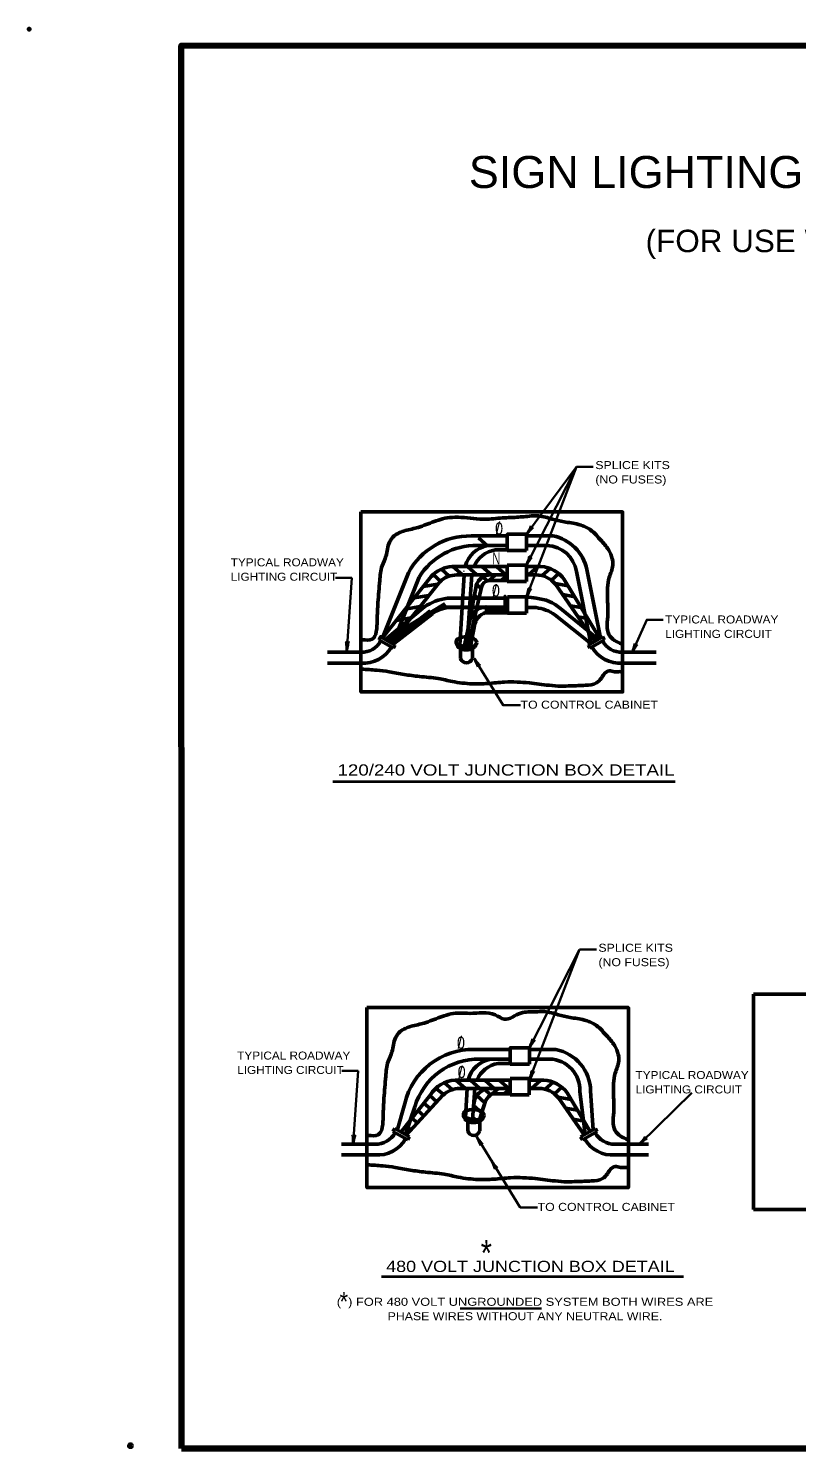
# Model space of a CAD drawing. Extents: x -38 to 818, y -13 to 531.
# Drawn here: x -38 to 250, y -2 to 531 of the extents above; entities that cross this region are included whole.
import ezdxf
from ezdxf.enums import TextEntityAlignment as Align

# ---------------------------------------------------------------- set-up
doc = ezdxf.new("R2010")
doc.units = 0
doc.header["$LTSCALE"] = 1.2
doc.header["$PDMODE"] = 32
doc.header["$PDSIZE"] = 0.6
doc.layers.add('1', color=7, linetype='Continuous', lineweight=53)

msp = doc.modelspace()

# ---------------------------------------------------------------- hatches: boundary and pattern name
at = {"layer": '1'}
for points in [[(0.944, -0.654, 1), (-0.256, -0.654, 1)], [(0.944, -0.654, 1), (-0.256, -0.654, 1)], [(1.089, -0.622, 1), (-0.111, -0.622, 1)], [(1.091, -0.622, 1), (-0.109, -0.622, 1)], [(1.121, -0.654, 1), (-0.079, -0.654, 1)], [(1.121, -0.654, 1), (-0.079, -0.654, 1)]]:
    msp.add_hatch(color=256, dxfattribs=at).paths.add_polyline_path(points)

# ---------------------------------------------------------------- linework, layer by layer
at = {"layer": '1', "lineweight": 35}
for p, q in [((167.736, 366.372), (148.989, 317.6)), ((167.736, 366.372), (174.011, 366.372)), ((83.465, 324.81), (77.293, 324.815)), ((81.538, 297.43), (83.465, 324.81)), ((168.893, 185.393), (150.071, 148.577)), ((168.893, 185.393), (150.146, 136.62)), ((168.893, 185.393), (175.168, 185.393)), ((85.898, 139.872), (79.726, 139.877)), ((83.97, 112.491), (85.898, 139.872)), ((191.422, 112.496), (210.938, 131.679)), ((124.08, 50.826), (154.633, 50.826))]:
    msp.add_line(p, q, dxfattribs=at)
at = {"layer": '1'}
for p, q in [((141.782, 341.134), (148.982, 341.134)), ((141.782, 341.134), (141.782, 335.015)), ((141.782, 341.134), (141.782, 335.015)), ((141.782, 341.134), (141.782, 335.015)), ((148.982, 341.134), (148.982, 335.015)), ((128.282, 340.491), (141.782, 340.491)), ((141.782, 336.891), (130.532, 336.891)), ((130.532, 336.891), (141.782, 336.891)), ((130.532, 336.891), (141.782, 336.891)), ((134.496, 336.652), (130.937, 339.805)), ((148.982, 340.491), (158.882, 340.491)), ((142.032, 335.247), (137.221, 335.247)), ((141.782, 335.015), (148.982, 335.015)), ((113.219, 325.292), (94.947, 302.337)), ((94.988, 302.314), (104.671, 326.655)), ((108.703, 325.05), (98.793, 300.139)), ((116.709, 323.553), (114.043, 325.915)), ((120.021, 325.428), (117.072, 328.041)), ((141.782, 329.013), (121.082, 329.013)), ((124.947, 325.873), (121.388, 329.027)), ((122.882, 325.873), (141.714, 325.873)), ((122.882, 325.873), (141.714, 325.873)), ((123.989, 299.51), (125.647, 325.873)), ((130.376, 325.873), (126.833, 329.013)), ((135.805, 325.873), (132.261, 329.013)), ((134.211, 323.646), (132.58, 325.091)), ((137.338, 325.873), (135.001, 323.803)), ((141.234, 325.873), (137.69, 329.013)), ((141.8, 325.873), (139.463, 323.803)), ((141.714, 329.556), (148.914, 329.556)), ((141.714, 329.556), (141.714, 323.437)), ((148.914, 329.556), (148.914, 323.437)), ((154.382, 329.013), (148.914, 329.013)), ((152.582, 325.873), (148.914, 325.873)), ((149.734, 325.873), (153.278, 329.013)), ((154.851, 325.597), (157.858, 328.261)), ((158.341, 323.88), (161.129, 326.349)), ((173.097, 300.165), (167.719, 327.102)), ((171.589, 327.875), (176.71, 302.229)), ((116.474, 323.315), (98.265, 300.441)), ((110.178, 321.471), (115.763, 322.422)), ((132.128, 321.254), (126.979, 298.623)), ((129.918, 320.961), (127.136, 305.98)), ((132.02, 320.778), (130.263, 322.334)), ((135.059, 323.803), (141.714, 323.803)), ((141.714, 323.437), (148.914, 323.437)), ((164.601, 321.77), (159.688, 322.606)), ((159.85, 322.372), (174.594, 301.02)), ((163.154, 324.179), (176.434, 302.071)), ((97.045, 302.095), (118.392, 315.057)), ((97.094, 302.015), (118.44, 314.978)), ((97.137, 301.943), (118.484, 314.905)), ((97.383, 301.538), (118.73, 314.501)), ((106.815, 317.247), (112.4, 318.198)), ((119.282, 317.091), (141.789, 317.091)), ((131.109, 316.775), (129.419, 318.273)), ((140.947, 314.153), (140.947, 314.375)), ((141.789, 317.6), (148.989, 317.6)), ((141.789, 317.6), (141.789, 311.48)), ((141.789, 317.6), (141.789, 311.48)), ((148.989, 317.6), (148.989, 311.48)), ((167.045, 317.702), (162.546, 318.468)), ((169.488, 313.634), (165.403, 314.329)), ((96.065, 301.698), (110.662, 313.885)), ((97.935, 300.629), (112.393, 310.537)), ((98.47, 301.209), (112.868, 312.357)), ((98.552, 301.102), (112.95, 312.25)), ((98.671, 300.949), (113.069, 312.097)), ((98.712, 300.896), (113.11, 312.044)), ((98.723, 300.882), (113.121, 312.03)), ((98.723, 300.882), (113.121, 312.03)), ((98.865, 300.699), (113.262, 311.847)), ((98.876, 300.685), (113.273, 311.833)), ((98.898, 300.656), (113.296, 311.804)), ((98.965, 300.569), (113.363, 311.717)), ((98.965, 300.569), (113.363, 311.717)), ((99.062, 300.445), (113.459, 311.593)), ((99.095, 300.401), (113.493, 311.55)), ((99.162, 300.315), (113.56, 311.463)), ((99.185, 300.286), (113.582, 311.434)), ((99.203, 300.262), (113.601, 311.41)), ((99.304, 300.132), (113.702, 311.28)), ((100.09, 308.798), (105.675, 309.749)), ((103.452, 313.022), (109.038, 313.973)), ((141.789, 313.592), (119.282, 313.592)), ((141.789, 313.592), (119.282, 313.592)), ((141.789, 313.592), (119.282, 313.592)), ((141.789, 313.592), (119.282, 313.592)), ((125.613, 298.909), (127.809, 309.303)), ((129.216, 311.767), (128.353, 312.532)), ((133.388, 313.483), (141.783, 313.519)), ((133.388, 313.483), (141.783, 313.519)), ((133.388, 313.414), (141.783, 313.451)), ((133.388, 313.346), (141.783, 313.383)), ((133.388, 313.346), (141.783, 313.382)), ((133.388, 313.329), (141.783, 313.365)), ((133.388, 313.329), (141.783, 313.365)), ((133.389, 313.295), (141.783, 313.331)), ((133.389, 313.278), (141.784, 313.314)), ((133.389, 313.243), (141.784, 313.28)), ((133.389, 313.175), (141.784, 313.211)), ((133.389, 313.141), (141.784, 313.177)), ((133.389, 313.141), (141.784, 313.177)), ((133.39, 313.056), (141.785, 313.092)), ((133.39, 312.987), (141.785, 313.024)), ((133.39, 312.935), (141.785, 312.972)), ((133.39, 312.936), (141.785, 312.972)), ((133.39, 312.919), (141.785, 312.955)), ((133.39, 312.902), (141.785, 312.938)), ((133.391, 312.85), (141.785, 312.887)), ((133.391, 312.782), (141.786, 312.819)), ((133.391, 312.765), (141.786, 312.801)), ((133.391, 312.748), (141.786, 312.784)), ((133.391, 312.748), (141.786, 312.784)), ((133.391, 312.748), (141.786, 312.784)), ((133.391, 312.696), (141.786, 312.733)), ((133.392, 312.645), (141.786, 312.682)), ((133.392, 312.628), (141.786, 312.665)), ((133.392, 312.577), (141.787, 312.614)), ((133.392, 312.577), (141.787, 312.614)), ((133.392, 312.543), (141.787, 312.579)), ((133.392, 312.475), (141.787, 312.511)), ((133.392, 312.475), (141.787, 312.511)), ((133.392, 312.458), (141.787, 312.494)), ((133.393, 312.389), (141.787, 312.426)), ((133.393, 312.338), (141.788, 312.374)), ((133.393, 312.321), (141.788, 312.357)), ((133.393, 312.287), (141.788, 312.324)), ((133.394, 312.202), (141.788, 312.238)), ((133.394, 312.201), (141.788, 312.238)), ((133.394, 312.168), (141.788, 312.204)), ((133.394, 312.167), (141.788, 312.203)), ((133.394, 312.133), (141.788, 312.169)), ((133.394, 312.081), (141.789, 312.118)), ((133.394, 312.03), (141.789, 312.067)), ((133.394, 312.013), (141.789, 312.05)), ((133.394, 311.997), (141.789, 312.033)), ((133.394, 311.98), (141.789, 312.016)), ((133.394, 311.962), (141.789, 311.998)), ((133.394, 311.946), (141.789, 311.982)), ((133.395, 311.894), (141.79, 311.931)), ((133.395, 311.86), (141.79, 311.897)), ((133.395, 311.843), (141.79, 311.88)), ((133.395, 311.792), (141.79, 311.828)), ((133.395, 311.74), (141.79, 311.777)), ((133.396, 311.723), (141.79, 311.76)), ((133.396, 311.658), (141.791, 311.694)), ((140.829, 312.024), (134.568, 311.997)), ((134.568, 311.997), (140.829, 312.024)), ((134.568, 311.997), (140.829, 312.024)), ((140.947, 311.661), (140.947, 313.592)), ((141.789, 311.48), (148.989, 311.48)), ((152.582, 313.592), (148.989, 313.592)), ((173.097, 300.165), (159.615, 310.908)), ((161.708, 313.238), (175.838, 301.731)), ((171.932, 309.566), (168.261, 310.191)), ((94.242, 302.74), (93.573, 301.567)), ((94.242, 302.74), (93.573, 301.567)), ((93.573, 301.567), (99.091, 298.414)), ((94.242, 302.74), (99.761, 299.586)), ((94.242, 302.74), (99.761, 299.586)), ((99.761, 299.586), (99.091, 298.414)), ((124.204, 294.659), (124.204, 298.259)), ((128.704, 294.659), (128.704, 298.259)), ((177.603, 302.74), (172.085, 299.586)), ((177.603, 302.74), (172.085, 299.586)), ((177.603, 302.74), (172.085, 299.586)), ((172.085, 299.586), (172.754, 298.414)), ((178.273, 301.567), (172.754, 298.414)), ((177.603, 302.74), (178.273, 301.567)), ((86.882, 296.841), (74.282, 296.841)), ((184.964, 296.841), (197.564, 296.841)), ((86.882, 292.791), (74.282, 292.791)), ((184.964, 292.791), (197.564, 292.791)), ((86.882, 281.991), (184.982, 281.991)), ((234.134, 168.699), (234.134, 87.931)), ((234.134, 168.699), (312.179, 168.699)), ((142.871, 147.934), (129.371, 147.934)), ((131.621, 144.334), (142.871, 144.334)), ((142.871, 144.334), (131.621, 144.334)), ((142.871, 148.577), (150.071, 148.577)), ((142.871, 148.577), (142.871, 142.458)), ((142.871, 148.577), (142.871, 142.458)), ((142.871, 142.458), (142.871, 148.577)), ((150.071, 142.458), (150.071, 148.577)), ((150.071, 144.334), (150.071, 147.934)), ((150.071, 144.334), (157.721, 144.334)), ((143.121, 142.69), (138.31, 142.69)), ((142.871, 142.458), (150.071, 142.458)), ((117.796, 130.998), (115.029, 133.449)), ((121.111, 132.871), (118.161, 135.484)), ((142.871, 136.456), (122.171, 136.456)), ((126.037, 133.316), (122.477, 136.47)), ((123.971, 133.316), (142.804, 133.316)), ((123.971, 133.316), (142.804, 133.316)), ((126.048, 122.375), (126.736, 133.316)), ((131.465, 133.316), (127.922, 136.456)), ((136.894, 133.316), (133.351, 136.456)), ((138.427, 133.316), (136.09, 131.246)), ((142.323, 133.316), (138.779, 136.456)), ((142.889, 133.316), (140.552, 131.246)), ((142.804, 136.999), (150.004, 136.999)), ((142.804, 136.999), (142.804, 130.88)), ((150.004, 136.999), (150.004, 130.88)), ((155.471, 136.456), (150.004, 136.456)), ((153.671, 133.316), (150.004, 133.316)), ((150.823, 133.316), (154.367, 136.456)), ((155.94, 133.04), (158.947, 135.704)), ((159.43, 131.322), (162.218, 133.792)), ((112.913, 130.888), (101.802, 116.945)), ((117.656, 130.846), (103.864, 115.751)), ((112.938, 125.682), (110.491, 127.85)), ((115.367, 128.34), (112.738, 130.669)), ((133.407, 127.957), (130.343, 130.671)), ((133.629, 128.666), (131.509, 121.911)), ((135.548, 130.87), (133.262, 132.895)), ((136.148, 131.246), (142.804, 131.246)), ((142.804, 130.88), (150.004, 130.88)), ((165.69, 129.213), (160.777, 130.049)), ((160.939, 129.815), (170.549, 115.898)), ((164.243, 131.622), (172.886, 117.233)), ((168.936, 132.23), (170.989, 116.149)), ((174.023, 117.715), (173.008, 132.387)), ((103.312, 127.679), (100.5, 117.596)), ((103.538, 116.185), (107.056, 126.4)), ((110.51, 123.024), (108.245, 125.031)), ((132.226, 124.194), (129.119, 126.946)), ((168.134, 125.145), (163.635, 125.911)), ((99.564, 118.324), (98.894, 117.152)), ((98.894, 117.152), (104.413, 113.998)), ((99.564, 118.324), (105.082, 115.171)), ((99.564, 118.324), (105.082, 115.171)), ((105.652, 117.708), (103.752, 119.392)), ((108.081, 120.366), (105.998, 122.211)), ((126.938, 117.463), (126.938, 121.063)), ((129.828, 121.508), (128.815, 122.406)), ((131.438, 117.463), (131.438, 121.063)), ((170.577, 121.077), (166.492, 121.772)), ((169.277, 115.171), (174.795, 118.324)), ((169.277, 115.171), (174.795, 118.324)), ((175.465, 117.152), (169.946, 113.998)), ((174.795, 118.324), (175.465, 117.152)), ((92.203, 112.425), (79.603, 112.425)), ((105.082, 115.171), (104.413, 113.998)), ((169.277, 115.171), (169.946, 113.998)), ((182.156, 112.425), (194.756, 112.425)), ((92.203, 108.375), (79.603, 108.375)), ((182.156, 108.375), (194.756, 108.375)), ((234.134, 87.931), (312.179, 87.931))]:
    msp.add_line(p, q, dxfattribs=at)
at = {"layer": '1', "lineweight": 40}
for p, q in [((76.351, 248.36), (204.723, 248.36)), ((94.579, 62.84), (207.84, 62.84))]:
    msp.add_line(p, q, dxfattribs=at)
at = {"layer": '1', "lineweight": 158}
msp.add_line((811.159, -1.718), (19.559, -1.718), dxfattribs=at)
msp.add_lwpolyline([(811.159, 524.382), (19.459, 524.282), (19.559, -1.718)], dxfattribs=at)
at = {"layer": '1', "lineweight": 35}
for points in [[(148.982, 341.134), (167.736, 366.372), (148.914, 329.556)], [(188.636, 296.795), (194.094, 309.054), (200.17, 309.054)], [(129.399, 294.55), (140.206, 277.026), (146.743, 277.026)], [(130.329, 115.13), (146.617, 88.718), (153.154, 88.718)]]:
    msp.add_lwpolyline(points, dxfattribs=at)
at = {"layer": '1'}
for points in [[(86.882, 349.491), (184.982, 349.491), (184.982, 281.991), (86.882, 281.991)], [(89.127, 163.64), (187.227, 163.64), (187.227, 96.14), (89.127, 96.14)]]:
    msp.add_lwpolyline(points, close=True, dxfattribs=at)
for points in [[(141.782, 335.015), (141.782, 341.134), (141.782, 335.015)], [(156.632, 336.891), (148.982, 336.891), (148.982, 340.491)], [(121.082, 329.013), (141.782, 329.013), (126.011, 329.013)], [(128.458, 325.873), (126.635, 298.728), (123.989, 299.51)], [(140.947, 311.661), (140.947, 317.78), (140.947, 311.661)], [(148.989, 311.48), (148.989, 317.6), (152.582, 317.091)], [(112.393, 310.537), (97.935, 300.629), (96.065, 301.698)], [(140.947, 313.773), (118.44, 313.773), (140.947, 313.773)], [(129.614, 307.558), (127.973, 299.006), (125.613, 298.909)], [(99.761, 299.586), (94.242, 302.74), (94.988, 302.314)], [(131.621, 144.334), (142.871, 144.334), (142.871, 142.458)], [(142.871, 142.458), (142.871, 148.577), (142.871, 142.458)], [(159.971, 147.934), (150.071, 147.934), (150.071, 144.334)], [(122.171, 136.456), (142.871, 136.456), (127.1, 136.456)], [(129.547, 133.316), (128.755, 121.519), (126.048, 122.375)]]:
    msp.add_lwpolyline(points, dxfattribs=at)
for centre in [(0.344, -0.654), (0.344, -0.654), (0.489, -0.622), (0.491, -0.622), (0.521, -0.654), (0.521, -0.654)]:
    msp.add_circle(centre, 0.6, dxfattribs=at)
for centre, radius, start, end in [((127.869, 314.132), 26.362, 89.10191, 151.63788), ((130.003, 311.823), 25.073, 88.79119, 148.16004), ((136.22, 326.497), 10.514, 99.33482, 166.15506), ((156.272, 325.31), 11.586, 8.89802, 88.21923), ((155.726, 324.604), 16.197, 11.64983, 78.7649), ((138.926, 324.872), 10.514, 99.33482, 156.80988), ((121.78, 317.37), 11.664, 93.43035, 137.21811), ((122.856, 316.634), 9.239, 89.83779, 133.68639), ((136.22, 326.497), 10.514, 175.66188, 175.86711), ((135.495, 320.29), 5.617, 99.31769, 173.13631), ((152.608, 316.634), 9.239, 38.39054, 90.16221), ((153.684, 317.37), 11.664, 35.7187, 86.56965), ((135.196, 320.686), 3.12, 92.52451, 169.51096), ((121.354, 298.324), 18.881, 96.30064, 124.49318), ((151.548, 301.905), 15.221, 48.12198, 86.10351), ((122.635, 293.357), 20.511, 99.4097, 120.64994), ((121.144, 300.098), 13.622, 97.85747, 129.97371), ((133.957, 307.426), 6.427, 80.69802, 163.0273), ((135.761, 305.681), 6.427, 100.69421, 163.0273), ((135.761, 305.681), 6.427, 100.69421, 163.0273), ((135.761, 305.681), 6.427, 100.69421, 163.0273), ((151.054, 299.031), 14.641, 54.21547, 84.00793), ((87.104, 305.115), 8.277, 268.46061, 331.14947), ((87.768, 304.916), 12.158, 265.82241, 330.12509), ((184.078, 304.916), 12.158, 209.87491, 274.17759), ((184.741, 305.115), 8.277, 208.85053, 271.53939), ((126.454, 295.245), 2.325, 194.60928, 345.39072), ((128.958, 121.574), 26.362, 89.10191, 166.6119), ((131.092, 119.266), 25.073, 88.79119, 163.46999), ((137.309, 133.939), 10.514, 99.33482, 166.15506), ((157.361, 132.753), 11.586, 357.41613, 88.21923), ((156.815, 132.047), 16.197, 1.20125, 78.7649), ((140.015, 132.315), 10.514, 99.33482, 156.80988), ((122.869, 124.813), 11.664, 93.43035, 148.6064), ((123.945, 124.077), 9.239, 89.83779, 132.89463), ((135.343, 127.136), 6.123, 84.95544, 184.27235), ((153.697, 124.077), 9.239, 38.39054, 90.16221), ((154.773, 124.813), 11.664, 35.7187, 86.56965), ((139.136, 125.809), 6.205, 118.7963, 152.57809), ((129.188, 118.05), 2.325, 194.60928, 345.39072), ((93.089, 120.5), 12.158, 265.82241, 330.12509), ((92.426, 120.699), 8.277, 268.46061, 331.14947), ((181.27, 120.5), 12.158, 209.87491, 274.17759), ((181.933, 120.699), 8.277, 208.85053, 271.53939)]:
    msp.add_arc(centre, radius, start, end, dxfattribs=at)
at = {"layer": '1', "lineweight": 40}
for centre, major_axis, ratio, start_param, end_param in [((149.497, 342.383), (-1.128, -1.832), 0.122415, 0.8963533, 3.1415927), ((149.988, 342.062), (-1.426, -1.566), 0.07063, 3.1407148, 5.41811), ((149.215, 330.873), (-0.809, -1.993), 0.122415, 0.8963533, 3.1415927), ((149.753, 330.638), (-1.147, -1.781), 0.07063, 3.1407148, 5.41811), ((149.15, 318.941), (-0.594, -2.067), 0.122415, 0.8963533, 3.1415927), ((149.709, 318.764), (0.953, 1.892), 0.07063, 6.2823074, 8.5597026), ((81.299, 298.759), (0.036, -2.151), 0.122415, 0.8963533, 3.1415927), ((81.885, 298.753), (0.358, 2.088), 0.07063, 6.2823074, 8.5597026), ((188.866, 298.126), (-0.7, -2.034), 0.122415, 0.8963533, 3.1415927), ((189.415, 297.92), (1.05, 1.84), 0.07063, 6.2823074, 8.5597026), ((129.889, 293.272), (0.927, -1.905), 0.07063, 6.2823074, 8.5597026), ((129.889, 293.272), (0.927, -1.905), 0.07063, 6.2823074, 8.5597026), ((130.368, 293.61), (-1.284, 1.726), 0.122415, 0.8963533, 3.1415927), ((130.368, 293.61), (-1.284, 1.726), 0.122415, 0.8963533, 3.1415927), ((150.372, 149.894), (-0.809, -1.993), 0.122415, 0.8963533, 3.1415927), ((150.909, 149.659), (-1.147, -1.781), 0.07063, 3.1407148, 5.41811), ((150.306, 137.962), (-0.594, -2.067), 0.122415, 0.8963533, 3.1415927), ((150.865, 137.784), (0.953, 1.892), 0.07063, 6.2823074, 8.5597026), ((83.731, 113.821), (0.036, -2.151), 0.122415, 0.8963533, 3.1415927), ((84.318, 113.815), (0.358, 2.088), 0.07063, 6.2823074, 8.5597026), ((130.818, 113.852), (0.927, -1.905), 0.07063, 6.2823074, 8.5597026), ((130.818, 113.852), (0.927, -1.905), 0.07063, 6.2823074, 8.5597026), ((131.298, 114.189), (-1.284, 1.726), 0.122415, 0.8963533, 3.1415927), ((131.298, 114.189), (-1.284, 1.726), 0.122415, 0.8963533, 3.1415927), ((192.123, 113.651), (-1.397, -1.636), 0.122415, 0.8963533, 3.1415927), ((192.559, 113.258), (1.651, 1.327), 0.07063, 6.2823074, 8.5597026), ((136.299, 104.965), (0.927, -1.905), 0.07063, 6.2823074, 8.5597026), ((136.779, 105.302), (-1.284, 1.726), 0.122415, 0.8963533, 3.1415927)]:
    msp.add_ellipse(centre, major_axis=major_axis, ratio=ratio, start_param=start_param, end_param=end_param, dxfattribs=at)
at = {"layer": '1'}
for centre in [(126.428, 300.654), (129.162, 123.458)]:
    msp.add_ellipse(centre, major_axis=(3.878, -0.144), ratio=0.757256, start_param=3.1415927, end_param=6.2831853, dxfattribs=at)
for centre in [(126.428, 300.654), (129.162, 123.458)]:
    msp.add_ellipse(centre, major_axis=(3.878, -0.144), ratio=0.505045, dxfattribs=at)
for points in [[(87.209, 301.575), (91.067, 301.795), (92.941, 308.742), (93.271, 315.578), (93.933, 323.738), (94.815, 329.251), (96.248, 332.889), (97.57, 338.182), (99.334, 340.498), (103.523, 342.483), (108.373, 343.695), (114.325, 345.901), (117.522, 346.893), (121.049, 347.444), (125.568, 347.334), (134.938, 346.783), (138.355, 347.114), (144.638, 347.444), (150.039, 347.886), (153.456, 347.996), (158.637, 346.783), (163.046, 345.79), (168.447, 344.798), (172.415, 343.144), (176.494, 339.285), (179.36, 335.867), (181.344, 329.471), (180.021, 324.951), (179.36, 317.122), (179.47, 314.255), (179.47, 310.285), (179.249, 305.985), (180.352, 302.788), (182.667, 300.913), (185.202, 299.81)], [(87.099, 290.548), (92.83, 290.107), (97.46, 289.556), (103.082, 288.563), (108.814, 287.792), (115.868, 287.02), (121.159, 285.917), (128.655, 285.035), (134.387, 285.145), (140.78, 285.697), (150.039, 285.366), (157.424, 284.484), (161.944, 284.153), (165.581, 284.263), (171.093, 284.484), (175.171, 285.366), (177.045, 287.13), (177.927, 288.563), (180.021, 289.887), (182.005, 289.556), (184.761, 289.446), (185.044, 289.314)], [(89.454, 115.724), (93.312, 115.944), (95.186, 122.891), (95.516, 129.727), (96.178, 137.887), (97.059, 143.4), (98.492, 147.038), (99.815, 152.331), (101.579, 154.647), (105.767, 156.631), (110.618, 157.844), (116.57, 160.05), (119.767, 161.042), (123.294, 161.593), (127.813, 161.483), (137.183, 160.932), (140.619, 159.339), (146.883, 161.593), (152.284, 162.034), (155.701, 162.145), (160.882, 160.932), (165.291, 159.939), (170.692, 158.947), (174.66, 157.293), (178.739, 153.434), (181.605, 150.016), (183.589, 143.62), (182.266, 139.099), (181.605, 131.271), (181.715, 128.404), (181.715, 124.434), (181.494, 120.134), (182.597, 116.937), (184.912, 115.062), (187.447, 113.959)], [(89.344, 104.697), (95.075, 104.256), (99.705, 103.705), (105.327, 102.712), (111.059, 101.941), (118.113, 101.169), (123.404, 100.066), (130.9, 99.184), (136.631, 99.294), (143.025, 99.846), (152.284, 99.515), (159.669, 98.633), (164.189, 98.302), (167.826, 98.412), (173.338, 98.633), (177.416, 99.515), (179.29, 101.279), (180.172, 102.712), (182.266, 104.036), (184.25, 103.705), (187.006, 103.594), (187.288, 103.462)]]:
    msp.add_spline(points, degree=3, dxfattribs=at)
msp.add_point((-37.541, 530.482), dxfattribs=at)

# ---------------------------------------------------------------- texts
for s, height, width, p in [('SIGN LIGHTING CONTROL CABINET WIRING DIAGRAMS', 12, 1.05, (127.345, 470.943)), ('(FOR USE WITH ROADWAY LIGHTING POWER SOURCE)', 8.4, 1.05, (193.641, 446.894)), ('SPLICE KITS', 3, 1.15, (174.79, 365.547)), ('(NO FUSES)', 3, 1.15, (174.79, 360.147)), ('0', 4.5, 0.9, (137.178, 341.035)), ('TYPICAL ROADWAY', 3, 1.1, (38.044, 329.086)), ('N', 4.5, 0.7, (136.132, 329.788)), ('LIGHTING CIRCUIT', 3, 1.1, (38.044, 323.686)), ('0', 4.5, 0.9, (136.001, 317.757)), ('TYPICAL ROADWAY', 3, 1.1, (201.001, 307.658)), ('LIGHTING CIRCUIT', 3, 1.1, (201.001, 302.258)), ('TO CONTROL CABINET', 3, 1.15, (146.743, 275.718)), ('120/240 VOLT JUNCTION BOX DETAIL', 4.2, 1.25, (78.094, 250.627)), ('SPLICE KITS', 3, 1.15, (175.946, 184.568)), ('(NO FUSES)', 3, 1.15, (175.946, 179.168)), ('0', 4.5, 0.9, (122.885, 148.205)), ('TYPICAL ROADWAY', 3, 1.1, (40.476, 144.147)), ('LIGHTING CIRCUIT', 3, 1.1, (40.476, 138.747)), ('0', 4.5, 0.9, (123.165, 137.218)), ('TYPICAL ROADWAY', 3, 1.1, (189.867, 136.852)), ('LIGHTING CIRCUIT', 3, 1.1, (189.867, 131.452)), ('TO CONTROL CABINET', 3, 1.15, (153.154, 87.41)), ('*', 9.6, 0.85, (131.786, 66.853)), ('480 VOLT JUNCTION BOX DETAIL', 4.2, 1.2, (96.322, 64.498)), ('*', 7.2, 0.85, (78.88, 49.815))]:
    msp.add_text(s, height=height, dxfattribs=dict(at, width=width)).set_placement(p)
for p in [(137.44, 341.166), (136.263, 317.757), (123.147, 148.336), (123.427, 137.218)]:
    msp.add_text('/', height=4.5, dxfattribs=at).set_placement(p)
for s, width, p in [('(  ) FOR 480 VOLT UNGROUNDED SYSTEM BOTH WIRES ARE', 1.2, (148.417, 51.823)), ('PHASE WIRES WITHOUT ANY NEUTRAL WIRE.', 1.15, (148.417, 46.423))]:
    msp.add_text(s, height=3, dxfattribs=dict(at, width=width)).set_placement(p, align=Align.CENTER)

doc.saveas('drawing.dxf')
